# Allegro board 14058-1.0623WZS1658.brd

Outline 205 x 270 mm; copper layers: TOP, L2GND, L3, L4, L5GND, BOTTOM. Coordinates in mm from the lower left corner of the outline.
Outline path: 0,268 0,64.98 arc(0.59,63.57) 2,62.98 11,62.98 arc(11.71,62.69) 12,61.98 12,23.98 arc(11.71,23.27) 11,22.98 2,22.98 arc(0.59,22.39) 0,20.98 0,2 arc(0.59,0.59) 2,0 184.26,0 arc(185.67,0.59) 186.26,2 186.26,13.2 arc(186.55,13.91) 187.26,14.2 188,14.2 arc(189.41,14.79) 190,16.2 190,58.1 arc(190.29,58.81) 191,59.1 192.5,59.1 arc(195.68,60.42) 197,63.6 197,65.1 arc(197.29,65.81) 198,66.1 201.17,66.1 arc(201.94,66.25) 202.59,66.69 204.41,68.51 arc(204.85,69.16) 205,69.93 205,101.21 arc(204.85,101.98) 204.41,102.63 203.5,103.54 202,103.54 arc(200.25,105.29) 202,107.04 203.5,107.04 204.41,107.95 arc(204.85,108.6) 205,109.37 205,156.77 arc(204.85,157.54) 204.41,158.19 201.59,161.01 arc(200.94,161.45) 200.17,161.6 191,161.6 arc(190.29,161.89) 190,162.6 190,227.2 arc(189.41,228.61) 188,229.2 187.48,229.2 arc(186.77,229.49) 186.48,230.2 186.48,258 arc(185.89,259.41) 184.48,260 147.48,260 arc(146.77,260.29) 146.48,261 146.48,268 arc(145.89,269.41) 144.48,270 2,270 arc(0.59,269.41) 0,268 ; 4.28,146.31 arc(6.53,148.56) 8.78,146.31 8.78,145.81 arc(6.53,143.56) 4.28,145.81 4.28,146.31 ; 43.96,265.47 arc(45.71,267.22) 47.46,265.47 arc(45.71,263.72) 43.96,265.47 ; 47.3,143.27 arc(49.3,145.27) 51.3,143.27 arc(49.3,141.27) 47.3,143.27 ; 47.36,231.27 arc(49.36,233.27) 51.36,231.27 arc(49.36,229.27) 47.36,231.27 ; 59.76,45.27 60.26,45.27 arc(62.51,43.02) 60.26,40.77 59.76,40.77 arc(57.51,43.02) 59.76,45.27 ; 63.78,134.01 arc(65.78,136.01) 67.78,134.01 arc(65.78,132.01) 63.78,134.01 ; 99.08,82.39 arc(101.08,84.39) 103.08,82.39 arc(101.08,80.39) 99.08,82.39 ; 99.3,143.23 arc(101.3,145.23) 103.3,143.23 arc(101.3,141.23) 99.3,143.23 ; 99.36,231.23 arc(101.36,233.23) 103.36,231.23 arc(101.36,229.23) 99.36,231.23 ; 120.91,89.85 arc(122.56,91.5) 124.21,89.85 arc(122.56,88.2) 120.91,89.85 ; 157.91,65.85 arc(159.56,67.5) 161.21,65.85 arc(159.56,64.2) 157.91,65.85 ; 182.68,224.47 arc(184.93,226.72) 187.18,224.47 187.18,223.97 arc(184.93,221.72) 182.68,223.97 182.68,224.47 ; 182.75,19.2 arc(185,21.45) 187.25,19.2 arc(185,16.95) 182.75,19.2 ; 190.74,63.65 arc(192.49,65.4) 194.24,63.65 arc(192.49,61.9) 190.74,63.65

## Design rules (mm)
constraint set DEFAULT: min track width 0.127, pair gap 0.102
net group AUD_LINK_BCLK: nets AUD_LINK_BCLK AUD_LINK_BCLK_R
net group AUDIO_IO_40: nets RING2 SLEEVE
net group AUDIO_POP-MW: nets TPA3113_SD1# TPA3131_FAULT#
net group CLKOUT_PCIE1N: nets CLKOUT_PCIE1N NGFF_REFCLKN0
net group CLKOUT_PCIE1P: nets CLKOUT_PCIE1P NGFF_REFCLKP0
net group CPU_24MHZ_R_DN: nets CPU_24MHZ_R_DN PCH_CPU_NSSC_CLK_DN
net group CPU_24MHZ_R_DP: nets CPU_24MHZ_R_DP PCH_CPU_NSSC_CLK_DP
net group DDR3_A_CTRL-MW: nets M_ODT_A0 M_ODT_A1
net group DPD_LANE0N: nets DP_LANE0N_C DPD_LANE0N
net group DPD_LANE0P: nets DP_LANE0P_C DPD_LANE0P
net group DPD_LANE1N: nets DP_LANE1N_C DPD_LANE1N
net group DPD_LANE1P: nets DP_LANE1P_C DPD_LANE1P
net group GND: nets GND_AUD SIO_AGND
net group GPU_ODT-MW: nets ODTA0 ODTA1
net group HDMI1_CK+: nets HDMI1_CK+ HDMI1_CK+_C
net group HDMI1_CK-: nets HDMI1_CK- HDMI1_CK-_C
net group HDMI1_D0+: nets HDMI1_D0+ HDMI1_D0+_C
net group HDMI1_D0-: nets HDMI1_D0- HDMI1_D0-_C
net group HDMI1_D1+: nets HDMI1_D1+ HDMI1_D1+_C
net group HDMI1_D1-: nets HDMI1_D1- HDMI1_D1-_C
net group HDMI1_D2+: nets HDMI1_D2+ HDMI1_D2+_C
net group HDMI1_D2-: nets HDMI1_D2- HDMI1_D2-_C
net group HDMI_PWR: nets V_5P0_HDMI_CONN V_5P0_HDMI_CONN_L
net group HSI_C_DN6: nets HSI_C_DN6 HSI_DN6
net group HSI_C_DP6: nets HSI_C_DP6 HSI_DP6
net group HSI_DN8: nets HSI_DN8 NGFF_PCIE0_RXN
net group HSI_DP8: nets HSI_DP8 NGFF_PCIE0_RXP
net group HSI_LAN_DN1_R: nets HSI_LAN_DN1_R HSI_LAN_DN5
net group HSI_LAN_DP1_R: nets HSI_LAN_DP1_R HSI_LAN_DP5
net group HSO_C_DN6: nets HSO_C_DN6 HSO_DN6
net group HSO_C_DP6: nets HSO_C_DP6 HSO_DP6
net group HSO_C_LAN_DN5: nets HSO_C_LAN_DN5 HSO_DN5
net group HSO_C_LAN_DP5: nets HSO_C_LAN_DP5 HSO_DP5
net group PCH_CPU_BCLK_DN: nets PCH_CPU_BCLK_DN PCH_CPU_BCLK_R_DN
net group PCH_CPU_BCLK_DP: nets PCH_CPU_BCLK_DP PCH_CPU_BCLK_R_DP
net group PCH_CPU_PCIBCLK_DN: nets PCH_CPU_PCIBCLK_DN PCH_CPU_PCIBCLK_R_DN
net group PCH_CPU_PCIBCLK_DP: nets PCH_CPU_PCIBCLK_DP PCH_CPU_PCIBCLK_R_DP
net group PEG_C_RXN0: nets PEG_C_RXN0 PEG_RXN0
net group PEG_C_RXN1: nets PEG_C_RXN1 PEG_RXN1
net group PEG_C_RXN2: nets PEG_C_RXN2 PEG_RXN2
net group PEG_C_RXN3: nets PEG_C_RXN3 PEG_RXN3
net group PEG_C_RXN4: nets PEG_C_RXN4 PEG_RXN4
net group PEG_C_RXN5: nets PEG_C_RXN5 PEG_RXN5
net group PEG_C_RXN6: nets PEG_C_RXN6 PEG_RXN6
net group PEG_C_RXN7: nets PEG_C_RXN7 PEG_RXN7
net group PEG_C_RXP0: nets PEG_C_RXP0 PEG_RXP0
net group PEG_C_RXP1: nets PEG_C_RXP1 PEG_RXP1
net group PEG_C_RXP2: nets PEG_C_RXP2 PEG_RXP2
net group PEG_C_RXP3: nets PEG_C_RXP3 PEG_RXP3
net group PEG_C_RXP4: nets PEG_C_RXP4 PEG_RXP4
net group PEG_C_RXP5: nets PEG_C_RXP5 PEG_RXP5
net group PEG_C_RXP6: nets PEG_C_RXP6 PEG_RXP6
net group PEG_C_RXP7: nets PEG_C_RXP7 PEG_RXP7
net group PEG_C_TXN0: nets PEG_C_TXN0 PEG_TXN0
net group PEG_C_TXN1: nets PEG_C_TXN1 PEG_TXN1
net group PEG_C_TXN2: nets PEG_C_TXN2 PEG_TXN2
net group PEG_C_TXN3: nets PEG_C_TXN3 PEG_TXN3
net group PEG_C_TXN4: nets PEG_C_TXN4 PEG_TXN4
net group PEG_C_TXN5: nets PEG_C_TXN5 PEG_TXN5
net group PEG_C_TXN6: nets PEG_C_TXN6 PEG_TXN6
net group PEG_C_TXN7: nets PEG_C_TXN7 PEG_TXN7
net group PEG_C_TXP0: nets PEG_C_TXP0 PEG_TXP0
net group PEG_C_TXP1: nets PEG_C_TXP1 PEG_TXP1
net group PEG_C_TXP2: nets PEG_C_TXP2 PEG_TXP2
net group PEG_C_TXP3: nets PEG_C_TXP3 PEG_TXP3
net group PEG_C_TXP4: nets PEG_C_TXP4 PEG_TXP4
net group PEG_C_TXP5: nets PEG_C_TXP5 PEG_TXP5
net group PEG_C_TXP6: nets PEG_C_TXP6 PEG_TXP6
net group PEG_C_TXP7: nets PEG_C_TXP7 PEG_TXP7
net group POWER_RTC_35_5: nets V_3P0_BAT_VREG VBAT2
net group PWR_81203_VSN: nets PWR_81203_VSN VCORE_VSS_SEN
net group PWR_81203_VSNA: nets PWR_81203_VSNA VCCGT_VSS_SEN
net group PWR_81203_VSPA: nets PWR_81203_VSPA VCCGT_VCC_SEN
net group SATAHDR_RX_DN2_EMI: nets SATA__RXN2_C SATAHDR_RX_DN2_EMI
net group SATAHDR_RX_DN3: nets SATA__RXN3_C SATAHDR_RX_DN3
net group SATAHDR_RX_DP2_EMI: nets SATA__RXP2_C SATAHDR_RX_DP2_EMI
net group SATAHDR_RX_DP3: nets SATA__RXP3_C SATAHDR_RX_DP3
net group SATAHDR_TX_DN2_EMI: nets SATA__TXN2_C SATAHDR_TX_DN2_EMI
net group SATAHDR_TX_DN3: nets SATA__TXN3_C SATAHDR_TX_DN3
net group SATAHDR_TX_DP2_EMI: nets SATA__TXP2_C SATAHDR_TX_DP2_EMI
net group SATAHDR_TX_DP3: nets SATA__TXP3_C SATAHDR_TX_DP3
net group SD_CLK_C_1: nets SD_CLK_C_1 SP3
net group SD_DAT0: nets SD_DAT0 SP2
net group SD_DAT1: nets SD_DAT1 SP1
net group SD_DAT2: nets SD_DAT2 SP6
net group SD_DAT3: nets SD_DAT3 SP5
net group SIDE_USB3_TX1+: nets USB3_TX1_C_DP USB3_TX1_EMI_DP
net group SIDE_USB3_TX1-: nets USB3_TX1_C_DN USB3_TX1_EMI_DN
net group SIDE_USB3_TX2+: nets USB3_TX2_C_DP USB3_TX2_EMI_DP
net group SIDE_USB3_TX2-: nets USB3_TX2_C_DN USB3_TX2_EMI_DN
net group USB_PCH_DN8: nets USB_PCH_DN8 USB_PCH_DN8_NN
net group USB_PCH_DN9: nets USB_PCH_DN9 USB_PCH_DN9_NN
net group USB_PCH_DN10: nets USB_PCH_DN10 USB_PCH_DN10_NN
net group USB_PCH_DP8: nets USB_PCH_DP8 USB_PCH_DP8_PP
net group USB_PCH_DP9: nets USB_PCH_DP9 USB_PCH_DP9_PP
net group USB_PCH_DP10: nets USB_PCH_DP10 USB_PCH_DP10_PP
net group USBP1N_EXT: nets USB_PCH_DN1 USBP1N_EXT
net group USBP1P_EXT: nets USB_PCH_DP1 USBP1P_EXT
net group USBP3N_EXT: nets USB_PCH_DN3 USBP3N_EXT
net group USBP3P_EXT: nets USB_PCH_DP3 USBP3P_EXT
net group USBP4N_EXT: nets USB_PCH_DN4 USBP4N_EXT
net group USBP4P_EXT: nets USB_PCH_DP4 USBP4P_EXT
net group USBP5N_EXT: nets USB_PCH_DN5 USBP5N_EXT
net group USBP5P_EXT: nets USB_PCH_DP5 USBP5P_EXT
net group USBP6N_EXT: nets USB_PCH_DN6 USBP6N_EXT
net group USBP6P_EXT: nets USB_PCH_DP6 USBP6P_EXT
net group VRD_6_12: nets H_VIDSCK H_VIDSOUT
net group AGND: nets CHG_AGND
net group ATI_SIGNAL_4.5_5-MW: nets SA0_DIM0 SA0_DIM1 SA1_DIM0 SA1_DIM1
net group AUD_LINK_SDO: nets AUD_LINK_SDO AUD_LINK_SDO_N AUD_LINK_SDO_R
net group AUDIO_AMP_15: nets AMP_SPKR_L AMP_SPKR_R AMP_SWITCH_C_L AMP_SWITCH_C_R PORTC_SPK_L PORTC_SPK_L_1 PORTC_SPK_R PORTC_SPK_R_1 SCALAR_OUT_L SCALAR_OUT_L_C SCALAR_OUT_R SCALAR_OUT_R_C SPEAKER1_L1 SPEAKER1_R1 SPKR_IN_L SPKR_IN_R TP3131_GVDD TPA3131_GAIN TPA3131_LINN TPA3131_LINN_1 TPA3131_MUTE TPA3131_PLIMIT TPA3131_RINN TPA3131_RINN_1 TPA3131_SYNC
net group AUDIO_DMIC_MW: nets AUD_DMIC_CLK AUD_DMIC_CLK_R AUD_DMIC_CLK_R_1 AUD_DMIC_DATA AUD_DMIC_DATA_R
net group AUDIO_HDA-MW: nets AUD_AZACPU_SCLK AUD_AZACPU_SCLK_R AUD_AZACPU_SDI AUD_AZACPU_SDI_R AUD_AZACPU_SDO AUD_AZACPU_SDO_R AUD_BEEP_C AUD_BEEP_R AUD_LINK_RST_N AUD_LINK_RST_N_R AUD_LINK_RST_R_N AUD_LINK_SDIN AUD_LINK_SDIN_1 AUD_LINK_SDO_1 AUD_LINK_SDO_R1 AUD_LINK_SYNC AUD_LINK_SYNC_R BUZZER_SPKR_R PCH_AUD_RST_N PCH_AUD_RST_N_1 SENSE_B SENSEA SENSEA_D SLEEVE_G SPDIF_IC
net group AUDIO_IO: nets AUD_GP3 EAPD_DEPOP HPOL_CON HPOR_CON HPOUT-JD HPOUT-L HPOUT-R LINE2-VREFO LINEOUT-JD LINEOUT-L LINEOUT-R LINEOUT_C-L LINEOUT_C-R LINEOUT_CON-L LINEOUT_CON-R MIC2-L MIC2-L-1 MIC2-R MIC2-R-1 MIC2-VREFO-L MIC2-VREFO-R
net group AUDIO_IO_REF: nets JDREF MIC-CAP VRP
net group AUDIO_SPK_CN: nets SPKR_L+_C SPKR_L+_SNB SPKR_L-_C SPKR_L-_SNB SPKR_OUT_L- SPKR_OUT_R+ SPKR_OUT_R- SPKR_R+_C SPKR_R+_SNB SPKR_R-_C SPKR_R-_SNB TPA3131_BSNL TPA3131_BSNR TPA3131_BSPL TPA3131_BSPR
net group CARDREADER-MW: nets CR_CLKREQ_N GPIO MS_INS# SD_CD# SD_CMD SD_WAKE# SD_WAKE#_IC SD_WP SP4 SP7
net group CHARGER_4_5-MW: nets AC_OK# AC_OK#_C AC_PROTECT
net group CLKA: nets CK_M_DDR0_A_DN CK_M_DDR0_A_DP CK_M_DDR1_A_DN CK_M_DDR1_A_DP
net group CLOCK-MW: nets CK_24M_SIO CLK_24M_SIO_C LPC_0_ESPI_CLK_EC LPC_CLK PCH_CLK_TO_LPC SUSCLK TP_CK_48M_SIO
net group CMDA: nets M_CAS_A_N M_MAA_A0 M_MAA_A1 M_MAA_A2 M_MAA_A3 M_MAA_A4 M_MAA_A5 M_MAA_A6 M_MAA_A7 M_MAA_A8 M_MAA_A9 M_MAA_A10 M_MAA_A11 M_MAA_A12 M_MAA_A13 M_MAA_A14 M_MAA_A15 M_RAS_A_N M_SBS_A0 M_SBS_A1 M_SBS_A2 M_WE_A_N
net group CMDB: nets M_CAS_B_N M_MAA_B0 M_MAA_B1 M_MAA_B2 M_MAA_B3 M_MAA_B4 M_MAA_B5 M_MAA_B6 M_MAA_B7 M_MAA_B8 M_MAA_B9 M_MAA_B10 M_MAA_B11 M_MAA_B12 M_MAA_B13 M_MAA_B14 M_MAA_B15 M_RAS_B_N M_SBS_B0 M_SBS_B1 M_SBS_B2 M_WE_B_N
net group CONVERTER_4_5-MW: nets LEDC_ISET LPF RT SSTCMP SSTCMP_1 STATUS
net group CONVERTER_10_10: nets ISEN1 ISEN2 ISEN3 ISEN4 ISW OZ554_PWM RTD2482_VREF RTN1 RTN2 RTN3 RTN4
net group CONVERTER_20_10: nets LDR LDR_1 OZ554_VIN
net group CPU_MISC-MW: nets CPU_THERMTRIP_N H_PM_SYNC_0 H_PRDY_N H_PREQ_N H_SKTOCC_N SKL_CNL_N VCCST_PWRGD
net group CPU_XDP-MW: nets H_TCK H_TDI H_TDO H_TMS H_TRST_N H_TRST_N_R ITP_PMODE PCH_JTAGX PRIM_XDP_JTAG_TCK_R SKL_PCUDEBUG_0 SKL_PCUDEBUG_1 SKL_PCUDEBUG_2 SKL_PCUDEBUG_3 SKL_PCUDEBUG_4 SKL_PCUDEBUG_5 SKL_PCUDEBUG_6 SKL_PCUDEBUG_7 SKL_PCUDEBUG_8 SKL_PCUDEBUG_9 SKL_PCUDEBUG_10 SKL_PCUDEBUG_11 SKL_PCUDEBUG_12 SKL_PCUDEBUG_13 SKL_PCUDEBUG_14 SKL_PCUDEBUG_15 SKL_XDP_MBP_0 SKL_XDP_MBP_1 XDP_PCUDERBUG_3 XDP_PWR_DEBUG
net group CPU_XDP_COMP_12_15: nets PCH_XDP_PRDY_R_N PCH_XDP_PREQ_R_N TPEV_CFG_RCOMP
net group CTRA: nets M_SCKE_A0 M_SCKE_A1 M_SCS_A_N0 M_SCS_A_N1
net group CTRLB: nets M_ODT_B0 M_ODT_B1 M_SCKE_B0 M_SCKE_B1 M_SCS_B_N0 M_SCS_B_N1
net group DATAA0: nets M_DATA_A0 M_DATA_A1 M_DATA_A2 M_DATA_A3 M_DATA_A4 M_DATA_A5 M_DATA_A6 M_DATA_A7 M_DQS_A_DN0 M_DQS_A_DP0
net group DATAA1: nets M_DATA_A8 M_DATA_A9 M_DATA_A10 M_DATA_A11 M_DATA_A12 M_DATA_A13 M_DATA_A14 M_DATA_A15 M_DQS_A_DN1 M_DQS_A_DP1
net group DATAA2: nets M_DATA_A16 M_DATA_A17 M_DATA_A18 M_DATA_A19 M_DATA_A20 M_DATA_A21 M_DATA_A22 M_DATA_A23 M_DQS_A_DN2 M_DQS_A_DP2
net group DATAA3: nets M_DATA_A24 M_DATA_A25 M_DATA_A26 M_DATA_A27 M_DATA_A28 M_DATA_A29 M_DATA_A30 M_DATA_A31 M_DQS_A_DN3 M_DQS_A_DP3
net group DATAA4: nets M_DATA_A32 M_DATA_A33 M_DATA_A34 M_DATA_A35 M_DATA_A36 M_DATA_A37 M_DATA_A38 M_DATA_A39 M_DQS_A_DN4 M_DQS_A_DP4
net group DATAA5: nets M_DATA_A40 M_DATA_A41 M_DATA_A42 M_DATA_A43 M_DATA_A44 M_DATA_A45 M_DATA_A46 M_DATA_A47 M_DQS_A_DN5 M_DQS_A_DP5
net group DATAA6: nets M_DATA_A48 M_DATA_A49 M_DATA_A50 M_DATA_A51 M_DATA_A52 M_DATA_A53 M_DATA_A54 M_DATA_A55 M_DQS_A_DN6 M_DQS_A_DP6
net group DATAA7: nets M_DATA_A56 M_DATA_A57 M_DATA_A58 M_DATA_A59 M_DATA_A60 M_DATA_A61 M_DATA_A62 M_DATA_A63 M_DQS_A_DN7 M_DQS_A_DP7
net group DATAB0: nets M_DATA_B0 M_DATA_B1 M_DATA_B2 M_DATA_B3 M_DATA_B4 M_DATA_B5 M_DATA_B6 M_DATA_B7
net group DATAB1: nets M_DATA_B8 M_DATA_B9 M_DATA_B10 M_DATA_B11 M_DATA_B12 M_DATA_B13 M_DATA_B14 M_DATA_B15
net group DATAB2: nets M_DATA_B16 M_DATA_B17 M_DATA_B18 M_DATA_B19 M_DATA_B20 M_DATA_B21 M_DATA_B22 M_DATA_B23
net group DATAB3: nets M_DATA_B24 M_DATA_B25 M_DATA_B26 M_DATA_B27 M_DATA_B28 M_DATA_B29 M_DATA_B30 M_DATA_B31
net group DATAB4: nets M_DATA_B32 M_DATA_B33 M_DATA_B34 M_DATA_B35 M_DATA_B36 M_DATA_B37 M_DATA_B38 M_DATA_B39
net group DATAB5: nets M_DATA_B40 M_DATA_B41 M_DATA_B42 M_DATA_B43 M_DATA_B44 M_DATA_B45 M_DATA_B46 M_DATA_B47
net group DATAB6: nets M_DATA_B48 M_DATA_B49 M_DATA_B50 M_DATA_B51 M_DATA_B52 M_DATA_B53 M_DATA_B54 M_DATA_B55
net group DATAB7: nets M_DATA_B56 M_DATA_B57 M_DATA_B58 M_DATA_B59 M_DATA_B60 M_DATA_B61 M_DATA_B62 M_DATA_B63
net group DDR3_A_VREF: nets DIMM_CA_CPU_VREF_A DIMM_CA_CPU_VREF_RC DIMM_CA_VREF_A DIMM_CA_VREF_A_L DIMM_DQ_CPU_VREF_A DIMM_DQ_CPU_VREF_A_1 DIMM_DQ_CPU_VREF_B_1 DIMM_DQ_R_VREF_A_L
net group DDR3_B_VREF: nets DIMM_CA_VREF_B DIMM_CA_VREF_B_L DIMM_DQ_CPU_VREF_B DIMM_DQ_R_VREF_A DIMM_DQ_R_VREF_B DIMM_DQ_VREF_B
net group DDR_VTT_CON: nets TS#_DIMM0_1
net group DDSP_B_TX_DN_0: nets DDSP_B_TX_DN_0 HDMI1_DATA_IC_N0 HDMI_LANE0_IC_DN
net group DDSP_B_TX_DN_1: nets DDSP_B_TX_DN_1 HDMI1_DATA_IC_N1 HDMI_LANE1_IC_DN
net group DDSP_B_TX_DN_2: nets DDSP_B_TX_DN_2 HDMI1_DATA_IC_N2 HDMI_LANE2_IC_DN
net group DDSP_B_TX_DN_3: nets DDSP_B_TX_DN_3 HDMI1_DATA_IC_N3 HDMI_LANE3_IC_DN
net group DDSP_B_TX_DP_0: nets DDSP_B_TX_DP_0 HDMI1_DATA_IC_P0 HDMI_LANE0_IC_DP
net group DDSP_B_TX_DP_1: nets DDSP_B_TX_DP_1 HDMI1_DATA_IC_P1 HDMI_LANE1_IC_DP
net group DDSP_B_TX_DP_2: nets DDSP_B_TX_DP_2 HDMI1_DATA_IC_P2 HDMI_LANE2_IC_DP
net group DDSP_B_TX_DP_3: nets DDSP_B_TX_DP_3 HDMI1_DATA_IC_P3 HDMI_LANE3_IC_DP
net group DEEPSLEEP_CON-MW: nets SLP_SUSB SUS_PWR_ACK SUS_WARNB
net group DISPLAY_DDC-MW: nets DDPB_CTRL_CLK DDPB_CTRL_DATA DDPC_CTRL_CLK DDPC_CTRL_DATA DDPD_CTRL_CLK DDPD_CTRL_DATA
net group DP_RCOMP: nets DP_RCOMP
net group FAN_PWM: nets BKLT_ADJ CPU_FAN_CTRL_SIO CPU_FAN_TACH_SIO DPLVDS_PWMIN DPLVDS_PWMOUT L_BKLTCTL LVDS_BL_ADJ LVDS_DET_B_C* PCH_BKLT_PWM_1 SIO_LVDS_BL_ADJ
net group FFS_4_5-MW: nets FALL_INT2 FFS_INT1 FFS_INT1_C FFS_INT1_SIO FFS_INT2 FFS_INT2_C FFS_INT2_Q
net group GPIO_4-MW: nets 2136_HPD_C ACPRESENT ADAPTOR_PSID_R BIST_DISABLE BIST_EN_INV BIST_EN_SIO BIST_ENABLE BIST_ENABLE_1 BIST_PIN25 BOARD1 BOARD2 BOARD3 CHAR_CTL1 CHAR_CTL2 CHAR_CTL3 CHAR_EN CHAR_ILIM_HI CHAR_ILIM_LO CHAR_ILIM_SEL CHAR_STATUS DDSP_B_HPD DDSP_B_HPD_CONN DPLVDS_HPD EAPD_DEPOP_1 EAPD_DEPOP_2_D EDID_RDY EDP_4_HPD GPU_THERMAL_INT IO_SMI_N JACK_PSID LAN_DISABLE_N LPC_PME_N LVDS_DET_A* LVDS_DET_B* ME_CNTL ME_CNTL1 ME_CNTL2 MPCIE_DISABLE_N N38680596 NGFF_BT_DISABLE NGFF_DETECT_PCIE NGFF_DETECT_PCIE_C NGFF_DETECT_USB NGFF_DETECT_USB_C OSD_BIST_N OSD_DN OSD_DN_IC OSD_DN_R OSD_MENU OSD_MENU_IC OSD_MENU_R OSD_MENU_SIO OSD_UP OSD_UP_IC OSD_UP_R PANEL_SEL1_CABLE_C PANEL_SEL1_CABLE_EC PANEL_SEL1_CABLE_S PANEL_SEL2_CABLE_C PANEL_SEL2_CABLE_EC PANEL_SEL2_CABLE_S PANEL_SEL3_CABLE_C PANEL_SEL3_CABLE_EC PANEL_SEL3_CABLE_S PCH_CHAR_CTL3 PCH_OSD_DN PCH_OSD_MENU PCH_OSD_UP PSID_D PSID_D_1 PSID_G PW_CLEAR PWRCN_DET_N SIO_HDD_LED SIO_HDD_LED_1 SKEW1 SKEW2 SKEW3 SLP_WLAN_N SPKR_DET SPKR_DET_C WEBCAM_DET
net group GPU_ADDRESS-MW: nets DRAM_RST MAA0 MAA1 MAA2 MAA3 MAA4 MAA5 MAA6 MAA7 MAA8 MAA9 MAA10 MAA11 MAA12 MAA13 MAA14
net group GPU_CTRL-MW: nets A_BA0 A_BA1 A_BA2 B_BA2 CASA# CKEA0 CKEA1 CSA0#_0 CSA0#_1 CSA1#_0 CSA1#_1 RASA# WEA#
net group GPU_DATA-MW: nets DQMA0 DQMA1 DQMA2 DQMA3 DQMA4 DQMA5 DQMA6 DQMA7 MDA0 MDA1 MDA2 MDA3 MDA4 MDA5 MDA6 MDA7 MDA8 MDA9 MDA10 MDA11 MDA12 MDA13 MDA14 MDA15 MDA16 MDA17 MDA18 MDA19 MDA20 MDA21 MDA22 MDA23 MDA24 MDA25 MDA26 MDA27 MDA28 MDA29 MDA30 MDA31 MDA32 MDA33 MDA34 MDA35 MDA36 MDA37 MDA38 MDA39 MDA40 MDA41 MDA42 MDA43 MDA44 MDA45 MDA46 MDA47 MDA48 MDA49 MDA50 MDA51 MDA52 MDA53 MDA54 MDA55 MDA56 MDA57 MDA58 MDA59 MDA60 MDA61 MDA62 MDA63
net group GPU_GPIO-MW: nets GPIO1_FBVDDQCTL GPIO2_BL_PWM GPIO3_PPEN_R GPIO4_BLEN GPIO5_PWM_VID_BOOT_EN GPIO6_FB_CLAMP_TGL_REQ GPIO7_3D_STEREO GPIO8_OVERT# GPIO9_ALERT# GPIO10_MEM_VREF_CTL GPIO11_PWM_VID GPIO12_AC_DETECT GPIO13_NVVDD_PSI
net group GPU_OTHER_4-6-MW: nets BUFRST_N CLKA0_AND CLKA1_AND FB_VREF FBA_DEBUG0 FBA_DEBUG1 GC6_FB_EN GPIO_FB_CLAMP_GPU GPU_TESTMODE GPU_THERM_SHUTDOWN_N GPU_THERM_SHUTDOWN_N_1 GPU_THERM_SHUTDOWN_N_2 GPU_VCC3_CTL IFPAB_PLLVDD_1 IFPAB_PLLVDD_2 IFPB_IOVDD IFPC_IOVDD IFPC_PLLVDD_1 IFPC_PLLVDD_2 IFPD_IOVDD IFPD_PLLVDD_1 IFPD_PLLVDD_2 IFPE_IOVDD IFPEF_PLLVDD_1 IFPEF_PLLVDD_2 IFPF_IOVDD JTAG_TCLK JTAG_TDI JTAG_TDO JTAG_TMS JTAG_TRST PEX_TERMP PEX_TSTCLK_OUT PEX_TSTCLK_OUT# STRAP0 STRAP1 STRAP2 STRAP3 STRAP4 STRAP_REF0 U15_ZQ U19_ZQ U35_ZQ U36_ZQ U9626_ZQ U9627_ZQ U9628_ZQ U9629_ZQ VID_PLLVDD
net group GPU_VREF: nets DACA_VREF VREFC_U20 VREFC_U22 VREFD_U20 VREFD_U22
net group GSPI-MW: nets LPSS_GSPI0_CLK LPSS_GSPI0_CS_N LPSS_GSPI0_MISO LPSS_GSPI0_MOSI LPSS_GSPI1_CS_N LPSS_GSPI1_MISO LPSS_GSPI1_MOSI
net group HDMI-MW: nets CE CE#_1 CFG DCIN_EN DDCBUF DDPB_CTRL_CLK_CONN DDPB_CTRL_DATA_CONN DDSP_C_HPD_CONN EQ HDMI1_SCL HDMI1_SCL_C HDMI1_SDA HDMI1_SDA_C HDMI_HDCP_READY HDMI_HPDET HDMI_SCL_IN HDMI_SDA_IN ISET PD_N PRE REXT
net group HSO_C_DN8: nets HSO_C_DN8 HSO_DN8 NGFF_PCIE0_TXN
net group HSO_C_DP8: nets HSO_C_DP8 HSO_DP8 NGFF_PCIE0_TXP
net group LAN_OTHER_4-5-MW: nets LAN_RSET LANCLK_REQ_U_N RTL_ISOLATE_N RTL_ISOLATE_N_1 RTL_ISOLATE_N_2
net group LED_10_6: nets LAN_LEDACT_R# LINK_ACTIVITY_N PB_IN_SW1 PCH_SATA_LED_1 PCH_SATA_LED_N PCH_SATA_LED_R PCH_SATA_LED_R_N PWR_LED_YELLOW_C PWR_LED_YELLOW_C2 SATA_LED_N_C_1 SIO_GREEN SIO_GREEN_PWM SIO_GREEN_R SIO_YELLOW SIO_YELLOW_IC SPEED_100*_CON SPEED_100_N SPEED_1000*_CON SPEED_1000_N SUS_LED_GREEN_C SUS_LED_GREEN_C2
net group LPC-MW: nets FWH_ID0 INIT_3V L_AD0 L_AD1 L_AD2 L_AD3 L_FRAME_N L_FRAME_N_R LPC_PME# LPCPD_N PME_N SER_IRQ SER_IRQ_LT_R
net group M_EVENT_4_5-MW: nets SIO_MEM_EVENT_L
net group NGFF_CLCCK-MW: nets NGFF_CLKREQ0_N NGFF_CLKREQ1_N SUSCLK_NGFF
net group NGFF_OTHER-MW: nets NGFF_ALERT_N NGFF_PEWAKE0_N NGFF_PEWAKE1_N NGFF_POWER_CTRL NGFF_POWER_CTRL_1 NGFF_W_DISABLE1_N NGFF_W_DISABLE2_N
net group OSCILLATION-MW: nets 14MHZ_IN_SCALAR 14MHZ_OUT_SCALAR LAN_XTALI LAN_XTALO PCH_RTCRST_DOWN PCH_RTCX1 PCH_RTCX2 RTCX_L XTAL_24M_PCH_IN XTAL_24M_PCH_OUT XTAL_OUTBUFF XTAL_SSFOUT XTALIN XTALOUT
net group OTHER_4_5-MW: nets 1117 ADJ +3VL +5VL +OPC_FUSEPRG +P1V0_PRIME_PCH_FUSE_2V8 +VCCFUSEPRG_R +VCCPGPPA ADAPTOR_PSID_SIO KDAT MCLK MDAT SYS_FAN_TACH1_1 SYS_FAN_TACH1_2 SYSTEM_FAN_PWM1_1 TP_DET
net group PANEL_CONTROL-MW: nets BKLT_EN BKLT_EN1 DPLVDS_BL_EN DPLVDS_PANEL_VCC LVDS_PU_5 LVDS_PU_6 LVDS_PU_24 PANEL_ON_1 PANEL_ON_2 PANEL_ON_3 PANEL_ON_4 PANEL_ON_5 PANEL_SEL1_CABLE PANEL_SEL2_CABLE PANEL_SEL3_CABLE S_LVDS_BL_EN SCALAR_SIO_PU
net group PCIE_PCIECLKRQ-MW: nets PCH_PCIECLKRQ1_N_1 PCH_SRCCLKREQ0 PCH_SRCCLKREQ0_N PCH_SRCCLKREQ1 PCH_SRCCLKREQ1_N PCH_SRCCLKREQ2 PCH_SRCCLKREQ2_N PCH_SRCCLKREQ3 PCH_SRCCLKREQ4 PCH_SRCCLKREQ5 PCH_SRCCLKREQ6 PCH_SRCCLKREQ7 PCH_SRCCLKREQ8 PCH_SRCCLKREQ9 PCH_SRCCLKREQ10 PCH_SRCCLKREQ11 PCH_SRCCLKREQ12 PCH_SRCCLKREQ13 PCH_SRCCLKREQ14 PCH_SRCCLKREQ15 PEX_CLKREQ
net group PCIE_RCOMP_8_15: nets PCIE_RCOMPN PCIE_RCOMPP PEG_COMP
net group PECI-MW: nets EC_PECI H_PECI PCH_PECI PECI_SIO
net group POWER_40_5: nets 3D3V_RUN_FFS HM_VCCP HM_VCCP_R SIO_AVCC3 SIO_MAIN_VCC3 SIO_VCORE V_1P5_PCH
net group POWER_40_10: nets PROG
net group POWER_50_5: nets 3V3_VDD33 +19V_AMP_AVCC ADC_1V2 AUD_DVDD BIST_PIN25_G LINK_PWR SP_PLLVDD TMDS_3V3 V_3P3_A_B V_5_CODEC V_CPU_EOPIO VCCK_1V2
net group PWM_10_10: nets +V1P0A_VCCAPLL +V1P0A_VCCF24_1P0 AD_IA AD_IA_HW1 AD_IA_HW1_C AD_IA_HW2 AD_IA_HW2_C AUD_LINK_RST_N_2 BIST_DISABLE_1 BIST_EN DDC5V_HDMI DDC5V_HDMI_R DDR_VREF_S3 DRVON EAPD_DEPOP_2 GPU_1D05V_FB GPU_VCC3_CTL_2 IFPA_IOVDD IMAX IMAXA LAN_DISABLE_N_1 LAN_DISABLE_N_2 LED_5VSB NCP81172_FB1 OPC_1P8_AB37 OSD_BIST_N_1 P1V0_PCH_VCCDSW PWM1A PWM2A PWR_1D0V_CS PWR_1D0V_EN PWR_1D0V_FB PWR_1D0V_FB_R PWR_1D0V_PG PWR_1D0V_RF PWR_3D3V_ENTRIP2 PWR_3D3V_FB PWR_3D3V_FB2 PWR_3D3V_LDO3 PWR_5V3V_EMN PWR_5V3V_LDO5 PWR_5V3V_PGOOD PWR_5V3V_TON PWR_5V_BYP1 PWR_5V_ENTRIP1 PWR_5V_FB1 PWR_12V_FB PWR_81203_COMP PWR_81203_COMP1 PWR_81203_COMP2 PWR_81203_COMPA PWR_81203_COMPA1 PWR_81203_COMPA2 PWR_81203_CSCOMP PWR_81203_CSCOMP1 PWR_81203_CSCOMPA PWR_81203_CSCOMPA1 PWR_81203_CSN3 PWR_81203_CSP1 PWR_81203_CSP1A PWR_81203_CSP2 PWR_81203_CSP2A PWR_81203_CSP3 PWR_81203_CSREF PWR_81203_CSREFA PWR_81203_CSSUM PWR_81203_CSSUMA PWR_81203_DIFF PWR_81203_DIFFA PWR_81203_FB PWR_81203_FBA PWR_81203_ILIM PWR_81203_ILIMA PWR_81203_IOUT PWR_81203_IOUTA PWR_81203_ROSC PWR_81203_TSEN PWR_81203_TSEN1 PWR_81203_TSENA PWR_81203_TSENA1 PWR_81203_VSP PWR_CHG_ACDET PWR_CHG_CMPIN PWR_CHG_CMPIN_R PWR_CHG_CMPIN_RR PWR_CHG_IOUT PWR_VCC_EN1 PWR_VCC_EN2 PWR_VCC_EN3 PWR_VCCIO_CS PWR_VCCIO_EN PWR_VCCIO_EN_G1 PWR_VCCIO_EN_G2 PWR_VCCIO_EN_R PWR_VCCIO_FB PWR_VCCIO_FB_R PWR_VCCIO_PG PWR_VCCIO_RF PWR_VCCSA_FB_L PWR_VCCSA_PG PWR_VDDQ_CS PWR_VDDQ_EN PWR_VDDQ_FB PWR_VDDQ_PG PWR_VDDQ_SENSE PWR_VDDQ_TON PWR_VDDQ_VTTREF PWR_VGA_CORE_COMP PWR_VGA_CORE_COMP_1 PWR_VGA_CORE_FB PWR_VGA_CORE_FBRTN PWR_VGA_CORE_FS PWR_VGA_CORE_PGOOD PWR_VGA_CORE_REFIN PWR_VGA_CORE_SENSE+_1 PWR_VGA_CORE_VID PWR_VGA_CORE_VIDBUF PWR_VGA_CORE_VREF PWR_VGA_CORE_VREF_1 PWR_VGA_CORE_VREF_2 PWR_VGT_EN1A PWR_VGT_EN2A Q28_B Q28_C SB3V_CT2 SB5V_CT1 SCALAR_PC_SW1 SCALAR_PC_SW2 SCALAR_PC_SW3 SCALAR_PC_SW4 SCALAR_PC_SW5 SIO_VREF TPA3113_SD VBAT_SIO VCC3_CT2 VCC5_DDC_HDMI VCC_CT1 VCC_RTCEXT_CAP VCCEOPIO_SENSE VCCGTX_SENSE VCCOPC_SENSE VREG_PCIAUX_PCH VREG_PCIAUX_PCH_1 VSS_OPC_EOPIO_SENSE VSSGTX_SENSE
net group PWM_12_12: nets CSN1 CSN2 CSN3 CSP1 CSP2 CSP3 PWM1 PWM2 PWM3 RREF
net group PWM_20_10: nets 3V3AUX +DVDDIO_AUDIO +VCCFUSEPRG +VCCPLL_OC +VCCPLL_OC_R AUD_REGREF AV12 BQ24737_REGN CBN CBP CPVEE DV12S DV33_18 HDMI_5V PVCC_3V3_SDRAM PWR_1D0V_BOOT PWR_1D0V_BOOT_R PWR_1D0V_SNB PWR_3D3V_BOOT2 PWR_3D3V_BOOT2_R PWR_3D3V_SNB PWR_5V3V_ENLDO PWR_5V_BOOT1 PWR_5V_BOOT1_R PWR_5V_SNB PWR_12V_BOOT PWR_12V_BOOT_R PWR_12V_SNB PWR_81203_VRMP PWR_CHG_BTST PWR_CHG_BTST_1 PWR_CHG_ILIM PWR_VCC_BST1 PWR_VCC_BST1R PWR_VCC_BST2 PWR_VCC_BST2R PWR_VCC_BST3 PWR_VCC_BST3R PWR_VCC_SNB1 PWR_VCC_SNB2 PWR_VCC_SNB3 PWR_VCC_VCC1 PWR_VCC_VCC2 PWR_VCC_VCC3 PWR_VCCIO_BOOT PWR_VCCIO_BOOT_R PWR_VCCIO_SNB PWR_VCCSA_BOOT PWR_VCCSA_BOOT_R PWR_VCCSA_COMP PWR_VCCSA_COMP_R PWR_VCCSA_CSP_R PWR_VCCSA_VCC PWR_VCCSA_VCCP PWR_VDDQ_BOOT PWR_VDDQ_BOOT_L PWR_VDDQ_SNB PWR_VDDQ_VDD PWR_VDDQ_VDDP PWR_VDDQ_VTTIN PWR_VGA_CORE_BOOT1 PWR_VGA_CORE_BOOT1_1 PWR_VGA_CORE_PVCC PWR_VGA_CORE_SNB PWR_VGA_CORE_TALERT# PWR_VGA_CORE_TSNS PWR_VGA_CORE_VCC PWR_VGA_VRAM_BOOT PWR_VGA_VRAM_BOOT_RC PWR_VGA_VRAM_FB PWR_VGA_VRAM_PFM PWR_VGA_VRAM_SNB PWR_VGA_VRAM_SS PWR_VGA_VRAM_TON PWR_VGA_VRAM_VCC PWR_VGT__BST1A PWR_VGT_BST1AR PWR_VGT_BST2A PWR_VGT_BST2AR PWR_VGT_SNB1A PWR_VGT_SNB2A PWR_VGT_VCC1A PWR_VGT_VCC2A RTD_PIN2 SDREG2 SIO_VIN1 SIO_VIN2 SIO_VIN3 SIO_VIN4 SIO_VIN5 VREF VREF_1
net group PWM_25_20: nets AD+_2 CORE_PLLVDD DACA_VDD FB_CAL_PD_VDDQ FB_CAL_PU_GND FB_CAL_TERM_GND FB_PLLAVDD GPU_3D3V_S0_THERM
net group PWM_30_12: nets HDD_LED_5V PCH_SATA_LED_2 PWR_CHG_VCC
net group PWM_40_25: nets PWR_1D0V_LGATE PWR_1D0V_UGATE PWR_3D3V_UGATE2 PWR_VCC_DRH1 PWR_VCC_DRH1_G PWR_VCC_DRH2 PWR_VCC_DRH2_G PWR_VCC_DRH3 PWR_VCC_DRH3_G PWR_VCC_DRL1 PWR_VCC_DRL2 PWR_VCC_DRL3 PWR_VCCSA_UGATE_R PWR_VDDQ_LGATE PWR_VDDQ_UGATE PWR_VGA_CORE_LGATE1 PWR_VGA_CORE_PSI PWR_VGA_CORE_UGATE1 PWR_VGA_CORE_UGATE1_R PWR_VGT_DRH1A PWR_VGT_DRH1A_G PWR_VGT_DRH2A PWR_VGT_DRH2A_G PWR_VGT_DRVLA1
net group PWM_PHASE: nets PWR_CHG_PHASE PWR_VCCIO_UGATE PWR_VCCSA_LGATE PWR_VCCSA_UGATE
net group PWR_EN_4-MW: nets +V_1P05_VGA_DISCHIG +V_1P35_VGA_DISCHG DGPU_PWR_EN DGPU_PWR_EN# GPU_1D05V_EN GPU_1D05V_PG GPU_1D05V_VGA_EN PWR_VCCIO_PG_D PWR_VGA_CORE_EN VGA_CORE_DISCHG
net group PWR_EN_4_10-MW: nets USB_EN USB_EN1 USB_EN2
net group PWR_VCCSA_FB: nets PWR_VCCSA_FB PWR_VCCSA_VSEN VCCSA_SENSE
net group PWRGD&RST_4-MW: nets ALL_PWRGD_2 ALL_SYS_PWRGD AMD_RST#_L BATLOW_N CPU_2_PCH_TRIGGER CPU_2_PCH_TRIGGER_R DDR0_ALERT# DDR1_ALERT# DDR3_DRAMRST_N DDR3_DRAMRST_N_A_1 DDR3_DRAMRST_N_B_1 DDR_SHDN DDR_VTT_CNTL DDR_VTT_CNTL_GATE FAN_CTRL_POWER FAN_OFF_D FAN_OFF_G FAN_OFF_G2 FP_RST_N FP_RST_PCH_N_CN GPU_PLTRST H_PM_DOWN H_PM_DOWN_R H_PM_SYNC H_PWRGD H_PWRGD_CPU H_RSTOUT_XDP_N ICH_RSMRST_N_R KBRST_N LAN_DISABLE_N_3 LAN_DISABLE_N_4 LAN_DISABLE_V3 LAN_WAKE_N LANWAKE_SMC_WAKE_SCI_N NGFF_POWER_CTRL_V2 OZ554_ENA PANEL_OFF PANEL_OFF_C PANEL_ON PANEL_ON1 PANEL_ON2 PANEL_ON3 PB_IN_N_1 PB_IN_N_1_C PC_MONITOR_SW PC_MONITOR_SW_G PCH_2_CPU_TRIGGER PCH_2_CPU_TRIGGER_R PCH_DPWROK PCH_HOT# PCH_PWROK PCH_SIO_DPWROK PCH_SLP_A_N PCH_SLP_S0_N PCH_SMI_N PCH_SYSPWROK PCH_THERMTRIP_N PCH_THERMTRIP_R_N PCH_WAKE_N PCIE_RST# PCIRST1# PCIRST3# PEX_RST_GPU PLTRST*_SIO PLTRST_CPU_N PLTRST_CR PLTRST_LAN_N PLTRST_N PLTRST_N_1A PLTRST_N_C PLTRST_N_CPU PLTRST_SL_N PM_PWRBTN_N PM_SLP_S3#_R PWM_SW_EN PWR_12V_EN PWR_12V_EN_G PWR_VCCIO_PG_G PWR_VCCSA_EN PWR_VGA_VRAM_POK PWR_VTT_EN PWRBTN_N PWRBTN_N_CN PWRGD_3V PWRGD_3V_B PWRGD_3V_B_1 PWRGD_3V_C PWRGD_3V_LL PWRGD_PS_L PWRGD_PS_L1 PWRGD_PS_L2 PWROK3_1 PWROK3_1_R PWROK3_2 PWROK3_2_R RSMRST*_R RSMRST_N RSMRST_N_B RTD_RESETB SB3V_EN SCALAR_EN SCALAR_EN_G SIO_AMD SVID_EN SIO_ATXPG SIO_GPU_EN SIO_GPU_RST SIO_PCIRSTIN# SIO_PSON_D SIO_PSON_N SLP_A#_CN SLP_S3_N SLP_S3_N_CN SLP_S3_N_R3 SLP_S4_N SLP_S4_N_C SLP_S4_N_CN SLP_S4_N_R SLP_S4_N_SFR SLP_S4_N_SFR_1 SLP_S4_N_SFR_2 SLP_S4_N_SFR_G SLP_S4_N_SIO SLP_S5_N SLP_SUSB_C SLP_SUSB_R SUS_PWR_ACK_SIO SUS_WARNB_SIO SW_ON_N SW_ON_N_SIO TP_SLP_LAN_N V_SM_1P5_EN VCC3_EN VCC_EN VCCST_PWRGD_CPU VCCST_PWRGD_L VR_ENABLE VR_ENABLE_IC VR_READY VR_READY_A VR_READY_G VR_READY_R VR_READY_Y VRALERTB_PU VTT_EN WAKE_N XDP_PLTRST_N XDP_PWRGD XDP_VR_READY
net group SCALAR-MW: nets BIOS_REQ DDC_WP DDC_WP_1 DET_HDMI# DET_HDMI_C HDMI_DET_SIO HDMI_IN_DET#_R HP_MUTE HP_MUTE_D HP_MUTE_L IMS OS_MODE_SEL OSD_CONTROL_SEL RTD_PIN105 RTD_PIN119 RTD_PIN123 RTD_PIN124 SCALAR_ACK SCALAR_MUTE SHDN_MUTE_AP_CTL
net group SIDE_USB3_RX1+: nets USB3_RX1_DP
net group SIDE_USB3_RX1-: nets USB3_RX1_DN
net group SIDE_USB3_RX2+: nets USB3_RX2_DP
net group SIDE_USB3_RX2-: nets USB3_RX2_DN
net group SIO_IT8731-4_5-MV-MW: nets EC_HDMI_PD_N EC_LAN_DISABLE_N EUP_DSW_SEL GPA7 GPU_ALLPWR KBCLK LDRQ# SIO_CE_N SIO_CLK_DB SIO_COPEN# SIO_DAT_DB SIO_HOLD# SIO_INT# SIO_K8PWR_EN SIO_SCK SIO_SCK_R SIO_SI SIO_SO SIO_UART1_RX SIO_UART1_RX_R SIO_UART1_TX SIO_UART1_TX_R SIO_WP# SIO_WRST# SYS_3VSB UART0_RX UART0_TX
net group SIO_IT8731-4_12-MW: nets A20GATE
net group SMBUS-MW: nets CHG_SMB2_CLK CHG_SMB2_DATA EESCL EESDA I2CC_SCL_PU I2CC_SDA_PU I2CS_SCL_G I2CS_SDA_G ISP_CLK1 ISP_DAT1 M1_SMB_CLK M1_SMB_DATA PCH_DVI_CLK PCH_DVI_DATA SIO_DEBUG_RX SIO_DEBUG_TX SIO_SMB2_CLK SIO_SMB2_DATA SIO_SMCLK0 SIO_SMDAT0 SMB0_CVT_CLK SMB0_CVT_DATA SMB_CLK_MAIN SMB_CLK_RESUME SMB_DATA_MAIN SMB_DATA_RESUME SMBUS_ISP SMLICLK_PCH SMLIDATA_PCH SMLINK0_CLK SMLINK0_DATA WP#_1 WP_PRO
net group SPI-MW: nets ROM_CS* ROM_CS_R* ROM_SI ROM_SI_R ROM_SO SDIN SDIN_1 SDOUT SO_1 SPI_CS0_N SPI_CS1_N SPI_MISO SPI_MISO_ROM_1 SPI_MOSI SPI_MOSI_1 SPI_WP_N_1 SST_HOLDJ_1
net group SPI_CLK-MW: nets CLK CLK_1 FLASH_WP ROM_SCLK ROM_SCLK_R SPI_CLK SPI_CLK_1 SPI_IO2 SPI_IO3 TP_GPP_D_21 TP_GPP_D_22 XDP_PRS
net group SVID-MW: nets CPU_VAIDALERT_N CPU_VIDSCK_N CPU_VIDSOUT_N PWR_81203_ALERT PWR_81203_SCLK PWR_81203_SDIO VIDALERT# VIDSCK VIDSOUT
net group SYS_POWER_12: nets SPKR
net group TP-MW: nets CPU_VSS_AB11 CPU_VSS_ABS DISP_UTIL_CPU GPP_E0 GPP_E1 GPP_E2 GPP_E3 GPP_E4 GPP_F0 GPP_F1 GPP_F2 GPP_F3 GPP_F4 GPP_G23 LED_DRIVE LPC_PIRQ_PU RSVD_AE17 RSVD_AF17 RSVD_AG14 RSVD_AG15 SMBALERT# SML0ALERT# THERMAL_SHUT#_SIO TP_AC37 TP_BD1 TP_BE2 TP_CPU_AU9 TP_CPU_AU10 TP_CPU_AU39 TP_CPU_AU40 TP_CPU_AV1 TP_CPU_AV39 TP_CPU_AW2 TP_CPU_AW38 TP_CPU_B39 TP_CPU_C40 TP_CPU_D15 TP_CPU_G38 TP_CPU_H11 TP_CPU_H12 TP_CPU_H37 TP_CPU_J7 TP_CPU_J8 TP_CPU_J11 TP_CPU_J13 TP_CPU_J14 TP_CPU_J15 TP_CPU_J17 TP_CPU_J19 TP_CPU_K8 TP_CPU_K10 TP_CPU_K11 TP_CPU_K12 TP_CPU_K13 TP_CPU_L8 TP_CPU_L10 TP_CPU_L12 TP_DDR0_PAR TP_DDR1_PAR TP_FM_OPC_ZVM_N TP_FPC_VREF TP_FPF_MON TP_GPP_A_8 TP_GPP_A_12 TP_GPP_B4 TP_GPP_B_0 TP_GPP_B_1 TP_GPP_B_11 TP_GPP_D_2 TP_GPP_F6 TP_GPP_F7 TP_GPP_F8 TP_GPP_G20 TP_GPP_G21 TP_GPP_G_12 TP_GPP_G_13 TP_GPP_G_14 TP_GPP_G_17 TP_GPP_H_10 TP_GPP_H_11 TP_GPP_H_12 TP_GPP_H_13 TP_GPP_H_14 TP_GPP_H_15 TP_GPP_H_16 TP_GPP_H_17 TP_GPP_H_18 TP_H_CATERR_N TP_L_BKLTEN TP_L_VDDEN TP_NGFF_COEX1 TP_NGFF_COEX2 TP_NGFF_COEX3 TP_NGFF_LED1 TP_NGFF_LED2 TP_NGFF_MLDIR TP_PCH_AB13 TP_PCH_AR22 TP_PCH_BD14 TP_PCH_C1 TP_PCH_D1 TP_SDI
net group TRANSFORNER_20_10: nets XRF_TDC2
net group USB_COMP-MW: nets USB2_COMP
net group USB_OC-MW: nets CHAR_USBOC# USB2_ID USB2_VBUSSENSE USB_OC0_R_N USB_OC4_R_N USB_OC5_R_N USB_OC6_R_N USB_OC7_R_N USBOC01* USBOC89* USBOC1011*
net group USBDN2_CHAR: nets USB_PCH_DN2_M USBDN2_CHAR USBP2N_EXT
net group USBDP2_CHAR: nets USB_PCH_DP2_M USBDP2_CHAR USBP2P_EXT
net group VBAT_RST_4_10-MW: nets PCH_INTRUDER_N PCH_RTCRST_PULLUP PCH_SRTCRSTB_PULLUP
net group VCC_SENSE: nets N1584333 V1P0_CPU_XDP_S5 V_CPU_ST_PLL V_CPU_VCCIO_R119BV VBOOT/ADDR VBOOTA/ADDRA VCCIO_SENSE
net group VCORE_SENSE-DIFF196: nets VCORE_VCC_SEN
net group VRD_4_12-MW: nets H_PROCHOT_N H_PROCHOT_N_SIO H_PROCHOT_R_N H_VIDALERT_N
net group WLAN_CLINK_4_10-MW: nets CLINK_CLK_LAN CLINK_CLK_LAN_1 CLINK_DATA_LAN CLINK_DATA_LAN_1 CLINK_RST_LAN_N CLINK_RST_LAN_N_1
net group XCLK_RCOMP-MW: nets XCLK_RBIAS
net group XDP-MW: nets PCH_JTAG_TCK PCH_JTAG_TDI PCH_JTAG_TDO PCH_JTAG_TMS

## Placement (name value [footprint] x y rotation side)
BT1  BAT-AAA-BAT-034-K01-GP  [AAA-BAT-034-K01]  133.38 110.1 180 top
BTRST1  PIN-CON2-S-GP  [210-41-02GB01]  140.92 123.93 270 top
C1  SCD1U16V2KX-3DLGP  [C402H22]  106.75 226.81 90 bottom
C2  SCD1U16V2KX-3DLGP  [C402H22]  114.62 224.14 0 bottom
C3  SCD022U16V2KX-3DLGP  [C402H22]  107.13 225.67 90 bottom
C4  SC22U6D3V3MX-1-DL-GP  [C603H40]  70.3 191.3 0 bottom
C5  SC22U6D3V3MX-1-DL-GP  [C603H40]  70.17 182.84 180 top
C6  SC22U6D3V3MX-1-DL-GP  [C603H40]  70.15 186.6 0 top
C7  SC22U6D3V3MX-1-DL-GP  [C603H40]  70.15 186.6 180 bottom
C8  SC22U6D3V3MX-1-DL-GP  [C603H40]  70.3 191.3 180 top
C9  SC22U6D3V3MX-1-DL-GP  [C603H40]  70.17 182.84 0 bottom
C10  SC22U6D3V5MX-2DLGP  [C805H54]  48.2 199.38 180 bottom
C11  SC22U6D3V5MX-2DLGP  [C805H54]  71.87 186.75 180 bottom
C12  SC22U6D3V5MX-2DLGP  [C805H54]  73.88 190.99 0 bottom
C13  SC22U6D3V5MX-2DLGP  [C805H54]  75.81 190.99 0 bottom
C14  SC22U6D3V5MX-2DLGP  [C805H54]  73.81 186.75 180 bottom
C15  SC22U6D3V5MX-2DLGP  [C805H54]  73.73 182.71 0 bottom
C16  SC22U6D3V5MX-2DLGP  [C805H54]  75.68 182.71 0 bottom
C17  SC22U6D3V5MX-2DLGP  [C805H54]  75.74 186.75 180 bottom
C18  SC22U6D3V5MX-2DLGP  [C805H54]  79.6 185.74 180 bottom
C19  SC22U6D3V5MX-2DLGP  [C805H54]  71.75 182.71 0 bottom
C20  SC22U6D3V5MX-2DLGP  [C805H54]  71.93 190.99 180 top
C21  SC22U6D3V5MX-2DLGP  [C805H54]  48.2 183.37 180 bottom
C22  SC22U6D3V5MX-2DLGP  [C805H54]  71.87 186.75 0 top
C23  SC22U6D3V5MX-2DLGP  [C805H54]  73.88 190.99 180 top
C24  SC22U6D3V5MX-2DLGP  [C805H54]  75.81 190.99 180 top
C25  SC22U6D3V5MX-2DLGP  [C805H54]  73.81 186.75 0 top
C26  SC22U6D3V5MX-2DLGP  [C805H54]  73.73 182.71 180 top
C27  SC22U6D3V5MX-2DLGP  [C805H54]  71.75 182.71 180 top
C28  SC22U6D3V5MX-2DLGP  [C805H54]  77.67 185.74 180 bottom
C29  SC22U6D3V5MX-2DLGP  [C805H54]  48.2 215.25 180 bottom
C30  SC22U6D3V5MX-2DLGP  [C805H54]  48.2 207.25 180 bottom
C31  SC22U6D3V5MX-2DLGP  [C805H54]  71.95 190.99 0 bottom
C32  SC22U6D3V5MX-2DLGP  [C805H54]  75.68 182.71 180 top
C33  SC22U6D3V5MX-2DLGP  [C805H54]  75.74 186.75 0 top
C34  SC22U6D3V5MX-2DLGP  [C805H54]  77.67 185.74 0 top
C35  SC22U6D3V5MX-2DLGP  [C805H54]  79.6 185.74 0 top
C36  SC22U6D3V5MX-2DLGP  [C805H54]  48.2 191.5 180 bottom
C37  SC22U6D3V5MX-2DLGP  [C805H54]  154.12 174.23 180 bottom
C38  SC22U6D3V3MX-1-DL-GP  [C603H40]  144.72 163.44 90 bottom
C39  SC22U6D3V3MX-1-DL-GP  [C603H40]  144.72 165.98 90 bottom
C40  SC22U6D3V3MX-1-DL-GP  [C603H40]  144.72 164.71 90 bottom
C41  SC22U6D3V5MX-2DLGP  [C805H54]  145.1 155.31 180 bottom
C42  SC22U6D3V5MX-2DLGP  [C805H54]  153.87 162.67 0 bottom
C43  SC22U6D3V5MX-2DLGP  [C805H54]  153.87 166.36 180 bottom
C44  SC22U6D3V5MX-2DLGP  [C805H54]  154.11 170.48 0 bottom
C45  SC22U6D3V3MX-1-DL-GP  [C603H40]  144.72 167.23 90 bottom
C47  SC22U6D3V5MX-2DLGP  [C805H54]  169.61 174.74 270 bottom
C48  SC22U6D3V5MX-2DLGP  [C805H54]  158.44 175.5 180 bottom
C49  SC22U6D3V5MX-2DLGP  [C805H54]  169.61 168.39 270 bottom
C50  SC22U6D3V5MX-2DLGP  [C805H54]  169.61 170.42 270 bottom
C51  SC22U6D3V5MX-2DLGP  [C805H54]  169.61 172.45 270 bottom
C52  SC47U6D3V5MX-1DL-GP  [C805H54]  71.95 227.19 270 top
C53  SC47U6D3V5MX-1DL-GP  [C805H54]  62.68 227.19 270 top
C54  SC47U6D3V5MX-1DL-GP  [C805H54]  67.13 227.19 270 top
C55  SC22U6D3V5MX-2DLGP  [C805H54]  71.93 195.08 0 top
C56  SC22U6D3V5MX-2DLGP  [C805H54]  73.86 195.08 0 top
C57  SC22U6D3V5MX-2DLGP  [C805H54]  75.79 195.08 0 top
C58  SC22U6D3V5MX-2DLGP  [C805H54]  77.72 195.08 0 top
C59  SC22U6D3V5MX-2DLGP  [C805H54]  79.65 195.08 0 top
C60  SC47U6D3V5MX-1DL-GP  [C805H54]  67.13 229.22 270 top
C61  SC22U6D3V5MX-2DLGP  [C805H54]  79.65 195.13 180 bottom
C62  SC22U6D3V5MX-2DLGP  [C805H54]  77.72 195.13 180 bottom
C63  SC22U6D3V5MX-2DLGP  [C805H54]  75.79 195.13 180 bottom
C64  SC47U6D3V5MX-1DL-GP  [C805H54]  62.68 229.22 270 top
C67  SC47U6D3V5MX-1DL-GP  [C805H54]  71.95 229.22 270 top
C68  SC47U6D3V5MX-1DL-GP  [C805H54]  71.95 229.22 90 bottom
C69  SC47U6D3V5MX-1DL-GP  [C805H54]  67.13 229.22 90 bottom
C70  SC22U6D3V5MX-2DLGP  [C805H54]  63.37 235.57 180 top
C71  SC22U6D3V5MX-2DLGP  [C805H54]  61.33 235.57 180 top
C72  SC22U6D3V5MX-2DLGP  [C805H54]  65.35 235.6 180 top
C73  SC22U6D3V5MX-2DLGP  [C805H54]  67.38 235.57 180 top
C74  SC22U6D3V5MX-2DLGP  [C805H54]  69.54 235.57 180 top
C75  SC22U6D3V5MX-2DLGP  [C805H54]  71.82 235.57 180 top
C76  SC22U6D3V5MX-2DLGP  [C805H54]  63.37 235.57 0 bottom
C77  SC22U6D3V5MX-2DLGP  [C805H54]  61.33 235.57 0 bottom
C78  SC22U6D3V5MX-2DLGP  [C805H54]  65.35 235.6 0 bottom
C79  SC22U6D3V5MX-2DLGP  [C805H54]  67.38 235.57 0 bottom
C80  SC22U6D3V5MX-2DLGP  [C805H54]  69.54 235.57 0 bottom
C81  SC22U6D3V5MX-2DLGP  [C805H54]  71.82 235.57 0 bottom
C82  SC22U6D3V5MX-2DLGP  [C805H54]  62.68 229.22 90 bottom
C83  SC1U10V2KX-1DLGP  [C402H22]  70.02 195.9 0 top
C84  SC22U6D3V3MX-1-DL-GP  [C603H40]  76.83 179.34 180 top
C85  SC22U6D3V3MX-1-DL-GP  [C603H40]  78.1 179.31 180 top
C86  SC22U6D3V5MX-2DLGP  [C805H54]  78.68 182.23 270 top
C87  SC22U6D3V5MX-2DLGP  [C805H54]  78.78 191.81 90 bottom
C88  SC22U6D3V5MX-2DLGP  [C805H54]  78.78 191.81 270 top
C89  SC22U6D3V5MX-2DLGP  [C805H54]  78.78 189.88 90 bottom
C90  SC22U6D3V5MX-2DLGP  [C805H54]  78.78 189.88 270 top
C91  SC22U6D3V5MX-2DLGP  [C805H54]  74.41 178.98 90 top
C92  SCD1U16V2KX-3DLGP  [C402H22]  169.6 164.94 270 bottom
C93  SCD1U16V2KX-3DLGP  [C402H22]  169.61 164.07 270 bottom
C94  SCD1U16V2KX-3DLGP  [C402H22]  169.61 163.18 270 bottom
C95  SCD1U16V2KX-3DLGP  [C402H22]  169.6 161.34 270 bottom
C96  SCD1U16V2KX-3DLGP  [C402H22]  159.45 159.63 90 bottom
C97  SC4D7U6D3V3KX-DLGP  [C603H36]  160.22 167.63 90 bottom
C98  SC4D7U6D3V3KX-DLGP  [C603H36]  160.22 166.36 90 bottom
C99  SC4D7U6D3V3KX-DLGP  [C603H36]  160.09 164.45 90 bottom
C100  SCD1U16V2KX-3DLGP  [C402H22]  169.61 162.29 270 bottom
C101  SC4D7U6D3V3KX-DLGP  [C603H36]  160.6 172.96 90 bottom
C102  SC4D7U6D3V3KX-DLGP  [C603H36]  160.6 171.69 90 bottom
C103  SC4D7U6D3V3KX-DLGP  [C603H36]  160.6 170.42 90 bottom
C104  SCD1U16V2KX-3DLGP  [C402H22]  164.79 135.75 0 bottom
C105  SCD1U16V2KX-3DLGP  [C402H22]  163.9 135.75 0 bottom
C106  SCD1U16V2KX-3DLGP  [C402H22]  169.61 166.74 270 bottom
C107  SCD1U16V2KX-3DLGP  [C402H22]  145.36 197.6 180 bottom
C108  SCD1U16V2KX-3DLGP  [C402H22]  144.47 197.6 180 bottom
C109  SC4D7U6D3V3KX-DLGP  [C603H36]  165.93 136.13 0 bottom
C110  SCD1U16V2KX-3DLGP  [C402H22]  167.07 135.75 0 bottom
C111  SCD022U16V2KX-3DLGP  [C402H22]  145.36 200.77 0 bottom
C112  SCD1U10V2KX-5DLGP  [C402H22]  153.49 189.85 90 bottom
C113  SCD1U16V2KX-3DLGP  [C402H22]  144.72 170.42 90 bottom
C114  SCD1U16V2KX-3DLGP  [C402H22]  153.62 159.51 90 bottom
C115  SCD1U16V2KX-3DLGP  [C402H22]  153.61 158.61 90 bottom
C116  SCD1U16V2KX-3DLGP  [C402H22]  144.72 169.53 90 bottom
C117  SCD1U16V2KX-3DLGP  [C402H22]  144.34 175.12 180 bottom
C118  SCD1U16V2KX-3DLGP  [C402H22]  144.98 173.6 90 bottom
C119  SCD1U16V2KX-3DLGP  [C402H22]  144.98 172.58 90 bottom
C120  SCD1U16V2KX-3DLGP  [C402H22]  144.72 168.64 90 bottom
C121  SC4D7U6D3V3KX-DLGP  [C603H36]  160.13 161.28 90 bottom
C122  SC4D7U6D3V3KX-DLGP  [C603H36]  160.09 162.55 90 bottom
C123  SC4D7U6D3V3KX-DLGP  [C603H36]  144.69 161.07 90 bottom
C124  SCD1U16V2KX-3DLGP  [C402H22]  143.33 175.12 180 bottom
C125  SC4D7U6D3V3KX-DLGP  [C603H36]  144.69 162.24 90 bottom
C126  SC4D7U6D3V3KX-DLGP  [C603H36]  161.36 174.99 180 bottom
C127  SC4D7U6D3V3KX-DLGP  [C603H36]  160.09 174.99 180 bottom
C128  SCD1U16V2KX-3DLGP  [C402H22]  146.75 136 0 bottom
C129  SCD1U16V2KX-3DLGP  [C402H22]  147.74 135.97 0 bottom
C130  SC4D7U6D3V3KX-DLGP  [C603H36]  144.34 137.65 0 bottom
C131  SCD1U16V2KX-3DLGP  [C402H22]  143.2 137.4 0 bottom
C132  SCD1U16V2KX-3DLGP  [C402H22]  169.61 165.85 270 bottom
C133  SCD1U16V2KX-3DLGP  [C402H22]  160.34 197.6 270 bottom
C134  SCD1U16V2KX-3DLGP  [C402H22]  160.34 196.71 270 bottom
C135  SCD022U16V2KX-3DLGP  [C402H22]  160.85 199 180 bottom
C136  SCD1U10V2KX-5DLGP  [C402H22]  168.85 190.11 90 bottom
C138  SCD1U16V2KX-3DLGP  [C402H22]  170.12 156.83 180 bottom
C139  SCD1U16V2KX-3DLGP  [C402H22]  169.23 156.83 180 bottom
C140  SC100P50V2JN-3DLGP  [C402H22]  149.7 88.58 270 bottom
C141  SC100P50V2JN-3DLGP  [C402H22]  155.26 91.81 270 bottom
C142  SC100P50V2JN-3DLGP  [C402H22]  152.6 91.68 90 bottom
C143  SCD1U16V2KX-3DLGP  [C402H22]  151.45 73.01 270 bottom
C144  SC100P50V2JN-3DLGP  [C402H22]  147.01 96.63 90 top
C145  SC1U10V2KX-1DLGP  [C402H22]  149.68 97.83 270 bottom
C146  SC1U10V2KX-1DLGP  [C402H22]  149.68 97.9 90 top
C147  SCD1U25V2KX-1-DL-GP  [C402H22]  148.15 101.21 270 top
C148  SC1U10V2KX-1DLGP  [C402H22]  86.18 79.49 90 top
C149  SC1U10V2KX-1DLGP  [C402H22]  156.28 57.39 0 top
C151  SC1U10V2KX-1DLGP  [C402H22]  156.79 55.87 270 top
C152  SC1U10V2KX-1DLGP  [C402H22]  91.28 86.83 270 bottom
C153  SCD1U16V2KX-3DLGP  [C402H22]  60.9 124.7 180 top
C156  SCD1U16V2KX-3DLGP  [C402H22]  152.19 61.71 90 top
C157  SC33P50V2JN-3DLGP  [C402H22]  122.88 71.74 180 top
C158  SC33P50V2JN-3DLGP  [C402H22]  123.13 68.44 0 top
C159  SC3P50V2CN-1-GP  [C402H22]  165.68 70.6 180 top
C160  SC3P50V2CN-1-GP  [C402H22]  165.68 68.44 0 top
C161  SCD1U16V2KX-3DLGP  [C402H22]  121.76 76.53 90 top
C162  SCD1U16V2KX-3DLGP  [C402H22]  121.76 77.39 90 top
C163  SCD01U25V2KX-3LLGP  [C402H22]  76.5 92.92 180 top
C165  SCD1U16V2KX-3DLGP  [C402H22]  125.54 76.16 90 top
C166  SCD1U16V2KX-3DLGP  [C402H22]  125.54 77.02 90 top
C167  SCD1U16V2KX-3DLGP  [C402H22]  124.25 80.95 90 top
C168  SCD1U16V2KX-3DLGP  [C402H22]  124.25 80.03 90 top
C169  SC1U10V2KX-1DLGP  [C402H22]  51.43 93.23 180 bottom
C171  SC1U10V2KX-1DLGP  [C402H22]  91.31 82.92 270 bottom
C172  SC1U10V2KX-1DLGP  [C402H22]  51.76 124.7 180 top
C173  SC1U10V2KX-1DLGP  [C402H22]  83.51 78.98 0 top
C179  SCD1U16V2KX-3DLGP  [C402H22]  94.43 54.47 90 top
C180  SCD1U10V2MX-3DLGP  [C402H22]  110.81 64.5 90 bottom
C181  SCD1U16V2KX-3DLGP  [C402H22]  96.03 52.97 180 top
C182  SCD1U10V2MX-3DLGP  [C402H22]  111.88 49.8 270 bottom
C183  SCD1U16V2KX-3DLGP  [C402H22]  102.81 52.31 0 bottom
C184  SCD1U16V2KX-3DLGP  [C402H22]  94.43 52.44 90 top
C185  SCD1U16V2KX-3DLGP  [C402H22]  105.61 64.38 90 bottom
C186  SC1U10V2KX-1DLGP  [C402H22]  101.29 48.25 180 top
C187  SC22U6D3V5MX-2DLGP  [C805H54]  96.97 46.6 90 top
C188  SC1U10V2KX-1DLGP  [C402H22]  101.92 53.33 180 bottom
C189  SCD1U16V2ZY-2DLGP  [C402H22]  118.86 56.58 180 bottom
C190  SC1U10V2KX-1DLGP  [C402H22]  99.64 67.04 270 top
C191  SCD1U16V2KX-3DLGP  [C402H22]  116.25 69 270 top
C193  SCD1U16V2KX-3DLGP  [C402H22]  119.25 51.29 270 bottom
C194  SCD1U16V2KX-3DLGP  [C402H22]  121.18 63.16 270 bottom
C195  SC22U6D3V5MX-2DLGP  [C805H54]  118.69 52.69 270 bottom
C197  SCD1U16V2ZY-2DLGP  [C402H22]  102.18 66.15 270 bottom
C199  SCD1U16V2KX-3DLGP  [C402H22]  104.34 59.68 0 bottom
C201  SC100P50V2JN-3DLGP  [C402H22]  92.14 61.71 90 top
C202  SC1U10V2KX-1DLGP  [C402H22]  166.57 89.65 270 top
C204  SC10U25V5KX-DL-GP  [C805H58]  12.52 166.23 90 top
C206  SC10U10V5KX-2DLGP  [C805H50]  184.22 66.03 0 top
C207  SCD1U16V2KX-3DLGP  [C402H22]  184.09 55.1 90 top
C208  SC10U10V5KX-2DLGP  [C805H50]  182.19 66.03 0 top
C209  SC1U10V2KX-1DLGP  [C402H22]  180.41 52.69 180 top
C210  SC1U10V2KX-1DLGP  [C402H22]  179.48 51.71 0 top
C211  SCD1U16V2KX-3DLGP  [C402H22]  182.06 63.36 270 bottom
C212  SC10U10V5KX-2DLGP  [C805H50]  181.55 64.88 270 bottom
C213  SCD1U16V2KX-3DLGP  [C402H22]  178.38 65.85 180 top
C214  SC10U10V5KX-2DLGP  [C805H50]  180.16 66.03 180 top
C215  SC10U10V5KX-2DLGP  [C805H50]  176.8 66.41 180 top
C216  SC220P50V2KX-3DLGP  [C402H22]  170.25 51.93 90 top
C217  SC100P50V2JN-3DLGP  [C402H22]  172.41 52.82 270 top
C218  SCD1U25V2KX-1-DL-GP  [C402H22]  172.51 64.54 90 top
C219  SCD1U16V2KX-3DLGP  [C402H22]  176.09 56.5 270 bottom
C220  SC10U6D3V3MX-DL-GP  [C603H36]  176.09 55.36 270 bottom
C221  SC10U6D3V3MX-DL-GP  [C603H36]  176.22 60.06 270 bottom
C222  SCD1U16V2KX-3DLGP  [C402H22]  173.17 57.52 0 top
C223  SC10U6D3V3MX-DL-GP  [C603H36]  172.03 57.14 0 top
C224  SC22P50V2JN-4DLGP  [C402H22]  172.79 59.3 270 top
C225  SC100P50V2JN-3DLGP  [C402H22]  170.48 62.9 270 top
C226  SC10U10V5KX-2DLGP  [C805H50]  181.55 66.92 270 bottom
C227  SC10U6D3V3MX-DL-GP  [C603H36]  176.09 54.09 270 bottom
C228  SCD1U16V2KX-3DLGP  [C402H22]  176.09 57.52 270 bottom
C229  SC10U6D3V3MX-DL-GP  [C603H36]  184.27 54.04 90 top
C230  SCD1U16V2KX-3DLGP  [C402H22]  181.81 52.95 270 top
C231  SC1KP50V2KX-1DLGP  [C402H22]  173.7 49.36 0 top
C232  SCD1U25V3KX-DLGP  [C603H36]  166.44 34.02 0 bottom
C233  SC10U25V5KX-DL-GP  [C805H58]  164.79 34.15 0 bottom
C234  SCD027U50V3KX-DL-GP  [C603H36]  180.92 37.2 0 top
C235  SCD22U16V3KX-2DLGP  [C603H36]  176.71 30.96 0 top
C236  SCD027U50V3KX-DL-GP  [C603H36]  179.65 37.17 0 top
C239  SCD22U16V3KX-2DLGP  [C603H36]  173.92 28.6 180 top
C240  SCD027U50V3KX-DL-GP  [C603H36]  171.57 41.93 0 top
C241  SCD027U50V3KX-DL-GP  [C603H36]  173.55 47.79 270 top
C242  SCD22U16V3KX-2DLGP  [C603H36]  170.27 28.85 270 top
C243  SC100P50V2JN-3DLGP  [C402H22]  172.69 49.36 0 top
C244  SCD22U16V3KX-2DLGP  [C603H36]  166.69 30.59 270 top
C245  SC1U16V3KX-2DLGP  [C603H36]  177.91 30.95 0 top
C246  SCD1U25V3KX-DLGP  [C603H36]  167.18 34.66 180 top
C247  SCD1U25V3KX-DLGP  [C603H36]  177.49 33.51 270 bottom
C248  SC10U25V5KX-DL-GP  [C805H58]  177.87 31.86 270 bottom
C249  SC1U25V3KX-1-DLGP  [C603H36]  175.65 40.36 0 top
C250  SC1U25V3KX-1-DLGP  [C603H36]  178 39.78 0 top
C251  SCD68U16V3KX-GP-U  [C603H36]  163.77 31.48 180 top
C252  SCD68U16V3KX-GP-U  [C603H36]  170.3 27.65 90 top
C253  SC1000P50V3JN-DLGP  [C603H36]  164.15 24.75 90 bottom
C254  SC1000P50V3JN-DLGP  [C603H36]  167.07 24.75 270 bottom
C255  SCD01U50V3JX-1GP  [C603]  162.12 24.24 0 bottom
C256  SCD01U50V3JX-1GP  [C603]  169.11 24.24 0 bottom
C257  SCD68U16V3KX-GP-U  [C603H36]  176.47 27.42 180 bottom
C258  SCD68U16V3KX-GP-U  [C603H36]  171.9 29.58 90 bottom
C259  SC1000P50V3JN-DLGP  [C603H36]  175.33 24.75 270 bottom
C260  SC1000P50V3JN-DLGP  [C603H36]  172.41 24.75 90 bottom
C261  SCD01U50V3JX-1GP  [C603]  177.36 24.24 0 bottom
C262  SCD01U50V3JX-1GP  [C603]  170.38 24.24 0 bottom
C263  SC4D7U6D3V3KX-DLGP  [C603H36]  182.95 69.65 90 top
C264  SC1KP50V2KX-1DLGP  [C402H22]  190.32 74.15 0 top
C265  SC4D7U6D3V3KX-DLGP  [C603H36]  185.68 69.19 90 top
C266  SC1KP50V2KX-1DLGP  [C402H22]  190.32 76.95 180 top
C267  SC100P50V2JN-3DLGP  [C402H22]  188.28 78.85 180 top
C268  SC100P50V2JN-3DLGP  [C402H22]  190.82 70.98 0 top
C269  SC1U10V2KX-1DLGP  [C402H22]  175.71 72.63 0 top
C270  SCD1U16V2KX-3DLGP  [C402H22]  103.93 40.14 0 top
C271  SC100P50V2JN-3DLGP  [C402H22]  102.56 37.83 180 top
C272  SC100P50V2JN-3DLGP  [C402H22]  102.56 35.8 0 top
C278  SCD1U16V2KX-3DLGP  [C402H22]  54.43 24.12 0 top
C279  SC2D2U10V3KX-1DLGP-U  [C603H36]  55.44 23.48 0 top
C280  SC1U10V2KX-1DLGP  [C402H22]  49.6 23.23 0 top
C281  SCD1U16V2KX-3DLGP  [C402H22]  57.6 24.62 0 top
C282  SC1U10V2KX-1DLGP  [C402H22]  51.38 47.48 270 top
C283  SC12P50V2JN-DL-GP  [C402H22]  55.95 30.97 0 top
C284  SC12P50V2JN-DL-GP  [C402H22]  55.95 33.01 180 top
C286  SC4D7U6D3V3KX-DLGP  [C603H36]  56.61 29.07 90 bottom
C287  SCD1U16V2KX-3DLGP  [C402H22]  60.24 29.98 180 bottom
C288  SCD1U16V2KX-3DLGP  [C402H22]  62.55 25.77 0 bottom
C289  SCD1U16V2KX-3DLGP  [C402H22]  59.35 26.63 270 bottom
C290  SCD1U16V2KX-3DLGP  [C402H22]  64.33 25.77 0 bottom
C291  SCD1U16V2KX-3DLGP  [C402H22]  63.44 25.77 0 bottom
C292  SCD1U16V2KX-3DLGP  [C402H22]  59.35 27.49 270 bottom
C294  SCD1U16V2KX-3DLGP  [C402H22]  58.74 22.85 90 bottom
C295  SCD1U16V2KX-3DLGP  [C402H22]  58.74 21.96 90 bottom
C296  SC4D7U6D3V3KX-DLGP  [C603H36]  62.93 21.58 0 bottom
C297  SC4D7U6D3V3KX-DLGP  [C603H36]  61.41 21.58 0 bottom
C298  SCD1U25V3KX-DLGP  [C603H36]  60.01 31.86 90 top
C299  SC4D7U6D3V3KX-DLGP  [C603H36]  60.01 33.13 90 top
C311  SC4D7U6D3V3KX-DLGP  [C603H36]  199.46 154.04 90 bottom
C312  SCD1U16V2KX-3DLGP  [C402H22]  199.84 155.18 270 bottom
C314  SCD1U16V2KX-3DLGP  [C402H22]  185.74 102.48 0 bottom
C324  SCD1U16V2KX-3DLGP  [C402H22]  184.6 143.12 90 bottom
C325  SCD1U16V2KX-3DLGP  [C402H22]  184.6 144 90 bottom
C329  SCD1U16V2KX-3DLGP  [C402H22]  180.03 141.46 180 bottom
C330  SC4D7U6D3V3KX-DLGP  [C603H36]  181.17 141.85 0 bottom
C331  SC10U10V5KX-2DLGP  [C805H50]  121.99 26.53 90 top
C332  SCD1U16V2KX-3DLGP  [C402H22]  122.12 21.83 90 top
C333  SC10U10V5KX-2DLGP  [C805H50]  122.12 24.37 90 top
C334  SC1KP50V2KX-1DLGP  [C402H22]  125.8 26.15 90 top
C338  SC1KP50V2KX-1DLGP  [C402H22]  135.2 25.77 90 top
C339  SCD1U16V2KX-3DLGP  [C402H22]  190.06 102.22 180 top
C340  SCD1U16V2KX-3DLGP  [C402H22]  122.12 22.85 90 top
C341  SCD1U16V2KX-3DLGP  [C402H22]  115.39 33.9 0 top
C342  SC10U10V5KX-2DLGP  [C805H50]  188.54 102.09 180 top
C343  SCD1U16V2KX-3DLGP  [C402H22]  189.3 119.87 180 top
C344  SC10U10V5KX-2DLGP  [C805H50]  185.74 119.75 180 top
C345  SC10U10V5KX-2DLGP  [C805H50]  187.78 119.75 180 top
C347  SCD1U16V2KX-3DLGP  [C402H22]  181.28 116.19 90 top
C348  SCD1U16V2KX-3DLGP  [C402H22]  181.28 117.07 90 top
C349  SCD1U16V2KX-3DLGP  [C402H22]  183.2 90.92 180 top
C350  SCD1U16V2KX-3DLGP  [C402H22]  182.19 90.92 180 top
C351  SC10U10V5KX-2DLGP  [C805H50]  176.22 202.55 90 top
C352  SC10U10V5KX-2DLGP  [C805H50]  176.22 204.58 90 top
C353  SCD1U16V2KX-3DLGP  [C402H22]  176.22 206.11 270 top
C355  SCD1U50V3KX-DL-GP  [C603H35]  85.29 27.16 270 bottom
C356  SCD1U16V2KX-3DLGP  [C402H22]  127.2 41.52 0 top
C357  SCD1U50V3KX-DL-GP  [C603H35]  79.83 38.67 270 top
C358  SC1U25V3KX-1-DLGP  [C603H36]  83.76 28.31 90 top
C362  SC1U10V2KX-1DLGP  [C402H22]  79.7 64.76 90 top
C363  SC10U10V5KX-2DLGP  [C805H50]  85.03 63.87 270 bottom
C364  SCD1U16V2KX-3DLGP  [C402H22]  85.29 62.34 270 bottom
C365  SC10U10V5KX-2DLGP  [C805H50]  86.3 69.2 0 bottom
C366  SCD1U16V2KX-3DLGP  [C402H22]  87.83 69.07 0 bottom
C367  SC1U6D3V2KX-DLGP  [C402H22]  76.52 66.79 270 top
C368  SC1U6D3V2KX-DLGP  [C402H22]  76.52 65.77 270 top
C369  SC1KP50V2KX-1DLGP  [C402H22]  85.01 66.79 270 bottom
C370  SC1KP50V2KX-1DLGP  [C402H22]  85.03 65.85 270 bottom
C371  SC1U10V2KX-1DLGP  [C402H22]  78.56 70.6 180 top
C372  SCD01U25V2KX-3DLGP  [C402H22]  81.68 56.98 180 top
C373  SCD1U50V3KX-DL-GP  [C603H35]  82.82 57.24 180 top
C374  SC10U10V5KX-2DLGP  [C805H50]  87.62 57.69 270 bottom
C375  SCD1U16V2KX-3DLGP  [C402H22]  87.85 54.98 270 bottom
C376  SC1U10V2KX-1DLGP  [C402H22]  77.41 52.82 180 bottom
C377  SC10U10V5KX-2DLGP  [C805H50]  71.57 46.85 180 bottom
C378  SC10U10V5KX-2DLGP  [C805H50]  67.38 51.93 180 bottom
C379  SCD1U16V2KX-3DLGP  [C402H22]  68.9 52.56 180 bottom
C380  SCD1U16V2KX-3DLGP  [C402H22]  69.28 45.73 180 bottom
C381  SC1U6D3V2KX-DLGP  [C402H22]  76.65 49.64 270 bottom
C382  SC1KP50V2KX-1DLGP  [C402H22]  68.19 49.72 90 bottom
C383  SC1KP50V2KX-1DLGP  [C402H22]  69.92 50.76 90 bottom
C384  SC1U10V2KX-1DLGP  [C402H22]  74.24 47.61 90 bottom
C412  SC10U6D3V3MX-DL-GP  [C603H36]  68.27 125.31 90 bottom
C413  SC10U6D3V3MX-DL-GP  [C603H36]  68.27 125.31 270 top
C414  SCD01U25V2KX-3DLGP  [C402H22]  97.73 115.94 90 top
C415  SCD1U16V2KX-3DLGP  [C402H22]  91.31 82.82 90 top
C417  SC22U6D3V5MX-2DLGP  [C805H54]  72.97 128.26 0 bottom
C418  SCD1U16V2KX-3DLGP  [C402H22]  52.77 124.7 180 top
C419  SCD1U16V2KX-3DLGP  [C402H22]  151.33 39.36 270 bottom
C420  SC22U6D3V5MX-2DLGP  [C805H54]  71.95 128.38 180 top
C421  SC10U6D3V3MX-DL-GP  [C603H36]  71.87 124.42 270 bottom
C426  SC22U6D3V5MX-2DLGP  [C805H54]  73.98 128.38 180 top
C427  SC4D7U25V5KX-DL-GP  [C805H54]  75.53 121.73 90 bottom
C428  SC1U25V3KX-1-DLGP  [C603H36]  75.28 118.81 270 bottom
C429  SC22U6D3V5MX-2DLGP  [C805H54]  70.94 128.26 0 bottom
C430  SC4D7U25V5KX-DL-GP  [C805H54]  75.13 123.68 90 bottom
C433  SC4D7U6D3V3KX-DLGP  [C603H36]  74.06 120.03 90 bottom
C434  SC1U10V2KX-1DLGP  [C402H22]  75.28 117.77 270 bottom
C435  SC1U25V3KX-1-DLGP  [C603H36]  78 122.11 0 bottom
C436  SC1KP50V2KX-1DLGP  [C402H22]  107.38 84.19 180 bottom
C437  SC4D7U6D3V3KX-DLGP  [C603H36]  72.08 120.61 180 bottom
C438  SC4D7U6D3V3KX-DLGP  [C603H36]  89.73 117.59 180 bottom
C440  SCD1U16V2KX-3DLGP  [C402H22]  88.08 117.59 0 bottom
C441  SC1U10V2KX-1DLGP  [C402H22]  82.75 117.05 270 bottom
